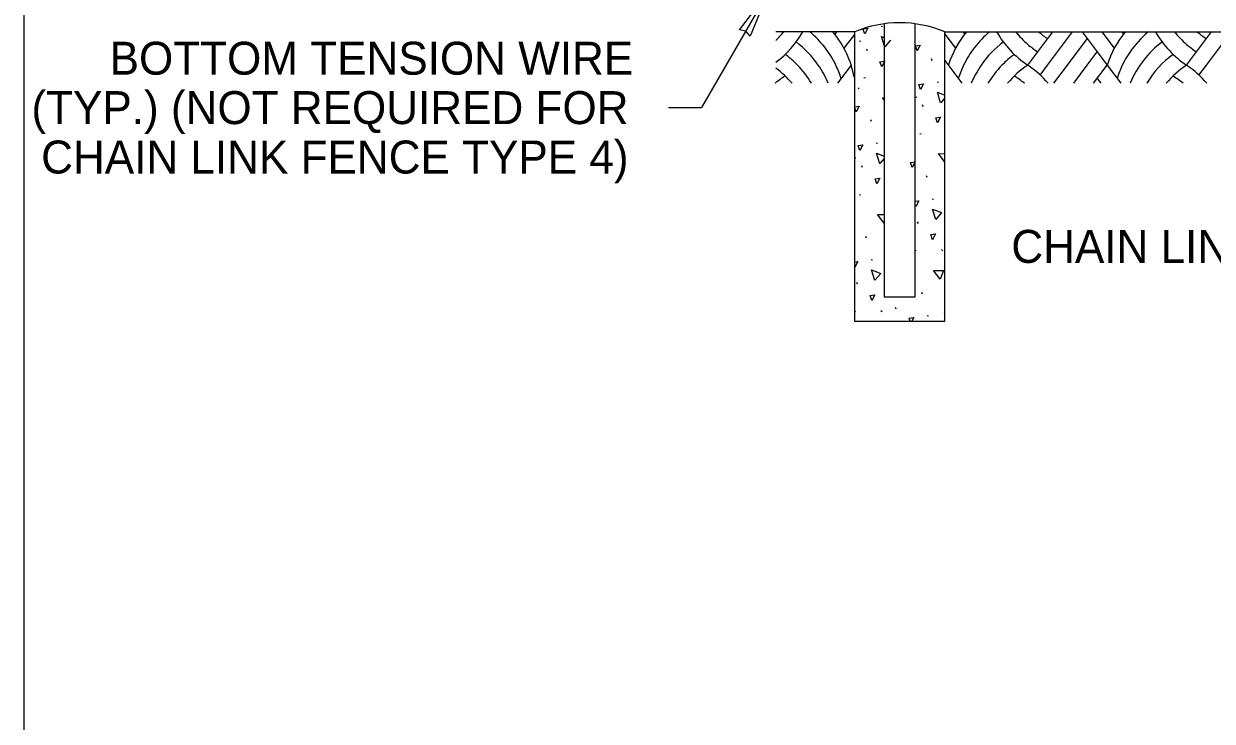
# Model space of a CAD drawing. Extents: x 99862 to 104211, y 98939 to 105076.
# Drawn here: x 99862 to 100439, y 100944 to 101283 of the extents above; entities that cross this region are included whole.
import ezdxf

# ---------------------------------------------------------------- set-up
doc = ezdxf.new("R2010")
doc.units = 0
for name, color, linetype in [('Level 1', 7, 'Continuous'), ('Level 10', 7, 'Continuous'), ('Level 15', 7, 'Continuous'), ('Level 20', 7, 'Continuous'), ('Level 6', 7, 'Continuous'), ('Level 7', 7, 'Continuous')]:
    doc.layers.add(name, color=color, linetype=linetype)

msp = doc.modelspace()

# ---------------------------------------------------------------- linework, layer by layer
at = {"layer": 'Level 1'}
msp.add_lwpolyline([(99862, 99999.5), (103151, 99999.5), (103151, 102075.5), (99862, 102075.5)], close=True, dxfattribs=at)
at = {"layer": 'Level 10'}
for p, q in [((100265.57, 101278.85), (100227.34, 101278.85)), ((100256.76, 101278.85), (100255.94, 101277.76)), ((100309.46, 101278.85), (100970.86, 101278.85)), ((100318.26, 101278.85), (100319.08, 101277.76)), ((100349.7, 101262.65), (100361.85, 101278.85)), ((100359.34, 101262.65), (100371.5, 101278.85)), ((100376.11, 101278.85), (100388.27, 101262.65)), ((100385.75, 101278.85), (100391.74, 101270.87)), ((100395.39, 101278.85), (100396.21, 101277.76)), ((100426.83, 101262.65), (100438.99, 101278.85)), ((100436.47, 101262.65), (100448.63, 101278.85)), ((100265.47, 101277.61), (100260.42, 101270.87)), ((100309.42, 101277.79), (100314.6, 101270.87)), ((100368.98, 101262.65), (100378.62, 101275.5)), ((100378.62, 101262.65), (100383.44, 101269.07)), ((100263.89, 101262.65), (100257.3, 101253.86)), ((100309.37, 101265), (100317.72, 101253.86)), ((100355.74, 101257.85), (100359.34, 101262.65)), ((100362.39, 101253.86), (100368.98, 101262.65)), ((100372.04, 101253.86), (100378.62, 101262.65)), ((100381.68, 101253.86), (100388.27, 101262.65)), ((100388.27, 101262.65), (100394.85, 101253.86)), ((100432.88, 101257.85), (100436.47, 101262.65)), ((100383.44, 101256.22), (100385.21, 101253.86))]:
    msp.add_line(p, q, dxfattribs=at)
for centre, start, end in [((100193.28, 101309.58), 314.26886, 320.98253), ((100198.1, 101303.15), 306.81514, 330.14307), ((100212.56, 101241.43), 25.7734, 50.08117), ((100217.39, 101247.86), 10.5451, 39.43727), ((100357.64, 101247.86), 140.56273, 162.30543), ((100362.46, 101241.43), 129.91883, 154.2266), ((100376.92, 101303.15), 209.85693, 236.09639), ((100381.74, 101309.58), 219.01747, 228.95992), ((100386.56, 101316), 229.57705, 236.09639), ((100434.77, 101247.86), 140.56273, 162.3566), ((100439.59, 101241.43), 129.91883, 162.35664), ((100454.05, 101303.15), 209.85693, 236.09639), ((100458.87, 101309.58), 219.01747, 228.95992), ((100463.69, 101316), 229.57705, 236.09639), ((100207.74, 101235), 34.50891, 52.8994), ((100367.28, 101235), 127.1006, 145.49109), ((100381.74, 101309.58), 228.95986, 236.09639), ((100444.41, 101235), 127.1006, 157.12457), ((100458.87, 101309.58), 228.95986, 236.09639), ((100202.92, 101228.57), 44.28722, 53.669), ((100372.1, 101228.57), 126.331, 135.71278), ((100449.23, 101228.57), 126.33095, 148.78462), ((100198.1, 101222.14), 40.53994, 53.18486), ((100202.92, 101228.57), 31.21538, 44.28731), ((100207.74, 101235), 22.73909, 34.50898), ((100212.56, 101241.43), 17.6434, 25.77346), ((100362.46, 101241.43), 154.22654, 162.3566), ((100367.28, 101235), 145.49102, 157.26091), ((100372.1, 101228.57), 135.71269, 148.78462), ((100376.92, 101222.14), 123.90361, 139.46006), ((100322.48, 101222.14), 40.53994, 56.09634), ((100454.05, 101222.14), 123.90361, 139.46006), ((100399.61, 101222.14), 40.53994, 56.09634), ((100257.36, 101215.72), 121.45354, 128.58357), ((100317.66, 101215.72), 51.41643, 58.54646), ((100394.79, 101215.72), 51.41643, 58.54646)]:
    msp.add_arc(centre, 48.8, start, end, dxfattribs=at)
at = {"layer": 'Level 15'}
for p in [(100223.62, 101298.08), (100175.25, 101242.02)]:
    msp.add_line(p, (100191.25, 101242.02), dxfattribs=at)
msp.add_lwpolyline([(100223.62, 101298.08), (100214.79, 101276.82), (100212.73, 101279.23), (100209.62, 101279.8)], close=True, dxfattribs=at)
at = {"layer": 'Level 6'}
for p, q in [((100265.57, 101278.85), (100265.57, 101138.38)), ((100278.47, 101281.64), (100279.13, 101281.51)), ((100309.46, 101138.38), (100309.46, 101278.85)), ((100267.97, 101274.47), (100268.62, 101274.34)), ((100271.79, 101269.65), (100271.47, 101270.5)), ((100303.32, 101264.82), (100302.99, 101265.67)), ((100270.15, 101256.59), (100270.81, 101256.46)), ((100305.63, 101254.48), (100306.29, 101254.35)), ((100295.12, 101247.31), (100295.78, 101247.18)), ((100298.95, 101242.49), (100298.62, 101243.34)), ((100273.76, 101235.26), (100273.43, 101236.12)), ((100297.31, 101229.43), (100297.97, 101229.3)), ((100276.08, 101224.92), (100276.73, 101224.79)), ((100265.57, 101217.75), (100266.22, 101217.62)), ((100269.39, 101212.93), (100269.07, 101213.79)), ((100300.92, 101208.1), (100300.59, 101208.96)), ((100267.75, 101199.87), (100268.41, 101199.74)), ((100303.23, 101197.76), (100303.89, 101197.63)), ((100296.55, 101185.77), (100296.22, 101186.63)), ((100271.36, 101178.55), (100271.03, 101179.4)), ((100294.91, 101172.72), (100295.57, 101172.58)), ((100307.84, 101173.05), (100308.5, 101172.53)), ((100273.68, 101168.21), (100274.33, 101168.08)), ((100266.99, 101156.22), (100266.67, 101157.07)), ((100298.52, 101151.39), (100298.19, 101152.24)), ((100265.57, 101143.12), (100266.01, 101143.03)), ((100278.28, 101143.5), (100278.94, 101142.97)), ((100285.86, 101144.11), (100285.53, 101144.96)), ((100300.83, 101141.05), (100301.49, 101140.92)), ((100309.46, 101142.11), (100309.34, 101142.41)), ((100265.57, 101138.38), (100309.46, 101138.38))]:
    msp.add_line(p, q, dxfattribs=at)
for points in [[(100270.52, 101277.93), (100269.67, 101280.36)], [(100269.69, 101280.37), (100271.96, 101280.69), (100270.52, 101277.93)], [(100279.97, 101272.33), (100278.65, 101276.63), (100279.97, 101276.13)], [(100283.03, 101274.83), (100280.29, 101271.58)], [(100295.95, 101269.59), (100295.1, 101272.02), (100297.39, 101272.35), (100295.95, 101269.59)], [(100295.95, 101269.59), (100295.1, 101272.02), (100297.39, 101272.35), (100295.95, 101269.59)], [(100278.75, 101261.77), (100277.9, 101264.2), (100280.19, 101264.53), (100278.75, 101261.77)], [(100267.76, 101251.09), (100267.55, 101251.7)], [(100297.68, 101250.78), (100296.82, 101253.21), (100299.12, 101253.53), (100297.68, 101250.78)], [(100307.38, 101244.36), (100305.8, 101249.47), (100309.46, 101248.08)], [(100279.97, 101245.81), (100279.19, 101246.84), (100279.97, 101246.82)], [(100309.46, 101246.81), (100307.44, 101244.42)], [(100265.57, 101242.47), (100267.83, 101242.79), (100266.39, 101240.03)], [(100266.39, 101240.03), (100265.57, 101242.38)], [(100305.91, 101234.61), (100305.05, 101237.04), (100307.35, 101237.37), (100305.91, 101234.61)], [(100268.12, 101221.22), (100267.27, 101223.65), (100269.56, 101223.98), (100268.12, 101221.22)], [(100277.82, 101214.8), (100276.25, 101219.92), (100279.97, 101218.49)], [(100279.97, 101217.33), (100277.89, 101214.86)], [(100293.55, 101212.88), (100292.7, 101215.3), (100294.99, 101215.63), (100293.55, 101212.88)], [(100309.46, 101215.58), (100306.35, 101219.68), (100309.46, 101219.63)], [(100276.35, 101205.06), (100275.5, 101207.48), (100277.79, 101207.81), (100276.35, 101205.06)], [(100295.01, 101196.57), (100296.72, 101196.82), (100295.28, 101194.06)], [(100295.28, 101194.06), (100295.01, 101194.81)], [(100304.98, 101187.64), (100303.41, 101192.76), (100307.87, 101191.05), (100305.04, 101187.71)], [(100280.02, 101185.85), (100276.79, 101190.12), (100279.97, 101190.07)], [(100303.51, 101177.9), (100302.65, 101180.33), (100304.95, 101180.66), (100303.51, 101177.9)], [(100265.57, 101167.03), (100267.16, 101167.26), (100265.72, 101164.51)], [(100265.72, 101164.51), (100265.57, 101164.94)], [(100275.42, 101158.08), (100273.85, 101163.2), (100278.31, 101161.5), (100275.49, 101158.15)], [(100307.18, 101158.69), (100303.95, 101162.96), (100308.73, 101162.89), (100307.22, 101158.78)], [(100273.95, 101148.34), (100273.1, 101150.77), (100275.39, 101151.1), (100273.95, 101148.34)], [(100292.52, 101138.38), (100292.02, 101139.78), (100294.32, 101140.1), (100293.42, 101138.38)]]:
    msp.add_lwpolyline(points, dxfattribs=at)
msp.add_arc((100287.51, 101226.19), 57.06, 67.38014, 112.61986, dxfattribs=at)
at = {"layer": 'Level 7'}
msp.add_lwpolyline([(100279.97, 101282.6), (100279.97, 101150.18), (100295.01, 101150.18), (100295.02, 101282.73)], dxfattribs=at)

# ---------------------------------------------------------------- texts
at = {"layer": 'Level 20'}
for s, p in [('BOTTOM TENSION WIRE', (99903.7, 101258.03)), ('(TYP.) (NOT REQUIRED FOR', (99865.74, 101234.03)), ('CHAIN LINK FENCE TYPE 4)', (99870.45, 101210.03))]:
    msp.add_text(s, height=16, dxfattribs=at).set_placement(p)
msp.add_text('CHAIN LINK FENCE FABRIC', height=16, rotation=360, dxfattribs=at).set_placement((100341.72, 101166.63))

doc.saveas('drawing.dxf')
